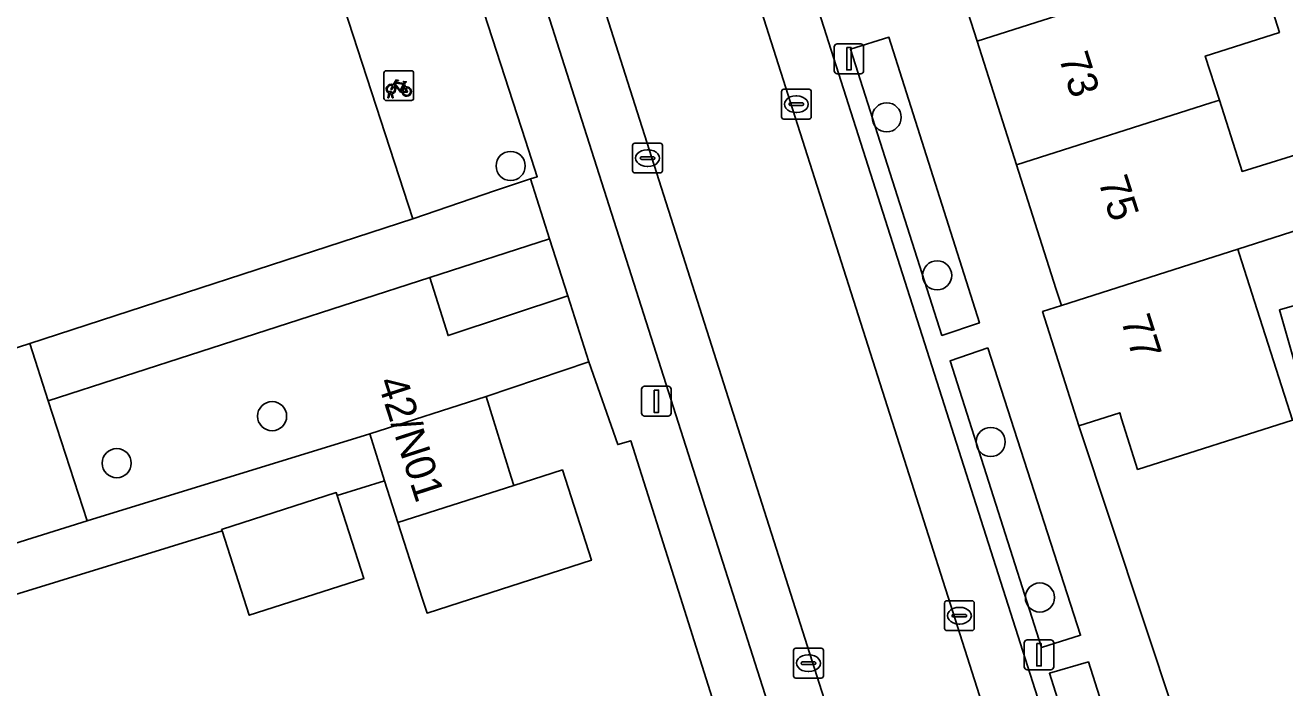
# Model space of a CAD drawing. Extents: x 159716 to 160783, y 383290 to 384031.
# Drawn here: x 160164.47 to 160206.79, y 383496.97 to 383519.22 of the extents above; entities that cross this region are included whole.
import ezdxf

# ---------------------------------------------------------------- set-up
doc = ezdxf.new("R2010")
doc.units = 0
for name, color, linetype in [('IMGEO_Boom', 7, 'Continuous'), ('IMGEO_Erf', 7, 'Continuous'), ('IMGEO_Fietsenrek', 7, 'Continuous'), ('IMGEO_Grasland_overig', 7, 'Continuous'), ('IMGEO_Groenvoorziening', 7, 'Continuous'), ('IMGEO_Kolk', 7, 'Continuous'), ('IMGEO_Lichtmast', 7, 'Continuous'), ('IMGEO_Pand', 7, 'Continuous'), ('IMGEO_Pand_nummerreeks', 7, 'Continuous'), ('IMGEO_Parkeervlak_open', 7, 'Continuous'), ('IMGEO_Rijbaan_lokaal_open', 7, 'Continuous'), ('IMGEO_Voetpad_open', 7, 'Continuous')]:
    doc.layers.add(name, color=color, linetype=linetype)

msp = doc.modelspace()

# ---------------------------------------------------------------- linework, layer by layer
at = {"layer": 'IMGEO_Boom'}
for centre in [(160193.412, 383516.124), (160180.78, 383514.491), (160195.107, 383510.818), (160172.767, 383506.09), (160196.907, 383505.224), (160167.549, 383504.512), (160198.56, 383499.999)]:
    msp.add_circle(centre, 0.489, dxfattribs=at)
at = {"layer": 'IMGEO_Erf'}
for points in [[(160205.752, 383521.653), (160206.607, 383518.975), (160204.116, 383518.179), (160204.587, 383516.705), (160205.353, 383514.305), (160207.805, 383515.062)], [(160208.524, 383512.755), (160205.207, 383511.696), (160205.253, 383511.552), (160205.858, 383509.657), (160207.04, 383505.953), (160201.843, 383504.304), (160201.304, 383506.003), (160201.241, 383506.203), (160199.868, 383505.763), (160203.111, 383495.995), (160207.309, 383482.802)], [(160207.828, 383505.379), (160206.604, 383509.664), (160210.537, 383510.788)], [(160150.634, 383478.026), (160168.912, 383473.579), (160192.457, 383481.099), (160186.486, 383500), (160184.817, 383505.264), (160184.377, 383505.133), (160183.402, 383507.916), (160179.961, 383506.748), (160180.803, 383504.044), (160180.889, 383503.767), (160182.522, 383504.282), (160183.493, 383501.254), (160179.435, 383499.947), (160177.973, 383499.476), (160177.821, 383499.947), (160176.993, 383502.519), (160176.547, 383503.922), (160174.954, 383503.431), (160175.851, 383500.643), (160171.999, 383499.403), (160171.086, 383502.238), (160163.828, 383500)]]:
    msp.add_lwpolyline(points, dxfattribs=at)
at = {"layer": 'IMGEO_Fietsenrek'}
for p, q in [((160176.598, 383517.689), (160177.439, 383517.689)), ((160177.439, 383517.689), (160176.598, 383517.689)), ((160176.523, 383516.764), (160176.523, 383517.605)), ((160176.523, 383517.605), (160176.523, 383516.764)), ((160177.21, 383517.238), (160177.246, 383517.143)), ((160177.523, 383517.614), (160177.523, 383516.773)), ((160177.523, 383516.773), (160177.523, 383517.614)), ((160176.65, 383516.773), (160176.689, 383516.933)), ((160176.719, 383516.921), (160176.684, 383516.773)), ((160176.761, 383516.945), (160176.76, 383516.949)), ((160176.802, 383516.773), (160176.768, 383516.915)), ((160176.792, 383516.956), (160176.793, 383516.949)), ((160176.8, 383516.919), (160176.835, 383516.773)), ((160177.448, 383516.689), (160176.607, 383516.689)), ((160176.607, 383516.689), (160177.448, 383516.689)), ((160176.684, 383516.773), (160176.65, 383516.773)), ((160176.835, 383516.773), (160176.802, 383516.773))]:
    msp.add_line(p, q, dxfattribs=at)
for points in [[(160176.836, 383517.215), (160176.931, 383517.379), (160177.017, 383517.365), (160177.019, 383517.356), (160176.963, 383517.345), (160176.936, 383517.3), (160177.192, 383517.259)], [(160177.179, 383517.234), (160176.922, 383517.275), (160176.905, 383517.246), (160177.072, 383517.026), (160177.179, 383517.234)], [(160177.192, 383517.259), (160177.217, 383517.308), (160177.211, 383517.312), (160177.188, 383517.316), (160177.176, 383517.323), (160177.175, 383517.326), (160177.177, 383517.331), (160177.272, 383517.316), (160177.274, 383517.306), (160177.264, 383517.293), (160177.252, 383517.287), (160177.238, 383517.293), (160177.21, 383517.238)], [(160176.857, 383517.163), (160176.805, 383517.073), (160176.765, 383517.048), (160176.766, 383517.095), (160176.821, 383517.189)], [(160177.132, 383516.971), (160177.082, 383516.971), (160176.891, 383517.222), (160176.872, 383517.19)], [(160177.227, 383517.136), (160177.197, 383517.213), (160177.088, 383516.995), (160177.131, 383516.995)], [(160177.161, 383516.995), (160177.281, 383516.994), (160177.237, 383517.108)], [(160177.257, 383517.115), (160177.312, 383516.97), (160177.162, 383516.97)]]:
    msp.add_lwpolyline(points, dxfattribs=at)
for centre, radius, start, end in [((160176.601, 383517.611), 0.0779, 92.4484, 184.2845), ((160176.601, 383517.611), 0.0779, 92.4484, 184.2845), ((160177.445, 383517.611), 0.0779, 2.4484, 94.2845), ((160177.445, 383517.611), 0.0779, 2.4484, 94.2845), ((160176.763, 383517.074), 0.159, 62.6766, 242.1369), ((160176.763, 383517.074), 0.129, 63.3192, 238.903), ((160176.743, 383516.945), 0.0499, 12.8025, 158.6934), ((160176.763, 383517.074), 0.159, 253.9967, 271.7867), ((160176.743, 383516.945), 0.0174, 12.8025, 163.4502), ((160176.763, 383517.074), 0.129, 253.415, 269.0204), ((160176.763, 383517.074), 0.129, 283.6043, 43.4302), ((160176.763, 383517.074), 0.159, 283.5766, 46.6042), ((160177.29, 383516.99), 0.159, 113.3408, 178.3217), ((160177.29, 383516.99), 0.159, 187.0065, 105.7708), ((160177.29, 383516.99), 0.129, 113.923, 177.9556), ((160177.29, 383516.99), 0.129, 188.6715, 104.5883), ((160176.601, 383516.767), 0.0779, 182.4484, 274.2845), ((160176.601, 383516.767), 0.0779, 182.4484, 274.2845), ((160177.445, 383516.767), 0.0779, 272.4484, 4.2845), ((160177.445, 383516.767), 0.0779, 272.4484, 4.2845)]:
    msp.add_arc(centre, radius, start, end, dxfattribs=at)
at = {"layer": 'IMGEO_Grasland_overig'}
for points in [[(160183.402, 383507.916), (160182.699, 383510.125), (160178.681, 383508.793), (160178.065, 383510.742), (160165.248, 383506.607), (160166.551, 383502.574), (160176.046, 383505.497), (160179.961, 383506.748)], [(160171.086, 383502.238), (160171.073, 383502.28), (160174.925, 383503.521), (160174.954, 383503.431), (160176.547, 383503.922), (160176.046, 383505.497), (160166.551, 383502.574), (160158.329, 383500), (160156.175, 383499.326), (160156.763, 383497.927), (160160.54, 383499.088), (160163.828, 383500)]]:
    msp.add_lwpolyline(points, close=True, dxfattribs=at)
at = {"layer": 'IMGEO_Groenvoorziening'}
for points in [[(160193.49, 383518.81), (160192.195, 383518.411), (160195.266, 383508.801), (160196.525, 383509.221)], [(160196.807, 383508.387), (160195.545, 383507.953), (160198.611, 383498.318), (160199.924, 383498.734)], [(160201.966, 383487.837), (160203.237, 383488.254), (160200.188, 383497.835), (160198.879, 383497.455), (160201.793, 383488.238)]]:
    msp.add_lwpolyline(points, close=True, dxfattribs=at)
at = {"layer": 'IMGEO_Kolk'}
for p, q in [((160189.878, 383516.138), (160189.878, 383516.99)), ((160189.953, 383517.064), (160190.805, 383517.064)), ((160190.366, 383516.844), (160190.391, 383516.844)), ((160190.879, 383516.99), (160190.879, 383516.138)), ((160190.137, 383516.558), (160190.137, 383516.57)), ((160190.575, 383516.521), (160190.177, 383516.521)), ((160190.18, 383516.607), (160190.578, 383516.607)), ((160190.621, 383516.57), (160190.621, 383516.558)), ((160190.805, 383516.064), (160189.953, 383516.064)), ((160190.389, 383516.284), (160190.364, 383516.284)), ((160184.878, 383514.329), (160184.878, 383515.181)), ((160184.953, 383515.255), (160185.805, 383515.255)), ((160185.879, 383515.181), (160185.879, 383514.329)), ((160185.137, 383514.749), (160185.137, 383514.761)), ((160185.575, 383514.712), (160185.177, 383514.712)), ((160185.18, 383514.798), (160185.578, 383514.798)), ((160185.366, 383515.035), (160185.391, 383515.035)), ((160185.621, 383514.761), (160185.621, 383514.749)), ((160185.389, 383514.475), (160185.364, 383514.475)), ((160185.805, 383514.255), (160184.953, 383514.255)), ((160195.43, 383499.89), (160196.282, 383499.89)), ((160195.355, 383498.964), (160195.355, 383499.816)), ((160195.843, 383499.67), (160195.868, 383499.67)), ((160196.356, 383499.816), (160196.356, 383498.964)), ((160195.614, 383499.384), (160195.614, 383499.396)), ((160196.052, 383499.347), (160195.654, 383499.347)), ((160195.657, 383499.433), (160196.055, 383499.433)), ((160195.866, 383499.11), (160195.841, 383499.11)), ((160196.098, 383499.396), (160196.098, 383499.384)), ((160196.282, 383498.89), (160195.43, 383498.89)), ((160190.285, 383497.37), (160190.285, 383498.222)), ((160190.36, 383498.296), (160191.212, 383498.296)), ((160191.286, 383498.222), (160191.286, 383497.37)), ((160190.544, 383497.79), (160190.544, 383497.802)), ((160190.587, 383497.839), (160190.985, 383497.839)), ((160190.773, 383498.076), (160190.798, 383498.076)), ((160191.028, 383497.802), (160191.028, 383497.79)), ((160190.982, 383497.753), (160190.584, 383497.753)), ((160190.796, 383497.516), (160190.771, 383497.516)), ((160191.212, 383497.296), (160190.36, 383497.296))]:
    msp.add_line(p, q, dxfattribs=at)
for points in [[(160189.878, 383516.138), (160189.878, 383516.99)], [(160189.953, 383517.064), (160190.805, 383517.064)], [(160190.879, 383516.99), (160190.879, 383516.138)], [(160190.805, 383516.064), (160189.953, 383516.064)], [(160184.878, 383514.329), (160184.878, 383515.181)], [(160184.953, 383515.255), (160185.805, 383515.255)], [(160185.879, 383515.181), (160185.879, 383514.329)], [(160185.805, 383514.255), (160184.953, 383514.255)], [(160195.43, 383499.89), (160196.282, 383499.89)], [(160195.355, 383498.964), (160195.355, 383499.816)], [(160196.356, 383499.816), (160196.356, 383498.964)], [(160196.282, 383498.89), (160195.43, 383498.89)], [(160190.285, 383497.37), (160190.285, 383498.222)], [(160190.36, 383498.296), (160191.212, 383498.296)], [(160191.286, 383498.222), (160191.286, 383497.37)], [(160191.212, 383497.296), (160190.36, 383497.296)]]:
    msp.add_lwpolyline(points, dxfattribs=at)
for centre, radius, start, end in [((160189.955, 383516.988), 0.0765, 91.552, 178.448), ((160189.955, 383516.988), 0.0765, 91.552, 178.448), ((160190.803, 383516.988), 0.0765, 1.552, 88.448), ((160190.803, 383516.988), 0.0765, 1.552, 88.448), ((160190.177, 383516.567), 0.0403, 85.8775, 175.7526), ((160190.174, 383516.557), 0.0366, 178.938, 274.7102), ((160190.578, 383516.564), 0.043, 264.8664, 352.4533), ((160190.582, 383516.569), 0.0386, 1.7309, 96.639), ((160189.955, 383516.14), 0.0765, 181.552, 268.448), ((160189.955, 383516.14), 0.0765, 181.552, 268.448), ((160190.803, 383516.14), 0.0765, 271.552, 358.448), ((160190.803, 383516.14), 0.0765, 271.552, 358.448), ((160184.955, 383515.179), 0.0765, 91.552, 178.448), ((160184.955, 383515.179), 0.0765, 91.552, 178.448), ((160185.803, 383515.179), 0.0765, 1.552, 88.448), ((160185.803, 383515.179), 0.0765, 1.552, 88.448), ((160185.177, 383514.758), 0.0403, 85.8775, 175.7526), ((160185.174, 383514.748), 0.0366, 178.938, 274.7102), ((160185.578, 383514.755), 0.043, 264.8664, 352.4533), ((160185.582, 383514.76), 0.0386, 1.7309, 96.639), ((160184.955, 383514.331), 0.0765, 181.552, 268.448), ((160184.955, 383514.331), 0.0765, 181.552, 268.448), ((160185.803, 383514.331), 0.0765, 271.552, 358.448), ((160185.803, 383514.331), 0.0765, 271.552, 358.448), ((160195.432, 383499.814), 0.0765, 91.552, 178.448), ((160195.432, 383499.814), 0.0765, 91.552, 178.448), ((160196.28, 383499.814), 0.0765, 1.552, 88.448), ((160196.28, 383499.814), 0.0765, 1.552, 88.448), ((160195.654, 383499.393), 0.0403, 85.8775, 175.7526), ((160195.651, 383499.383), 0.0366, 178.938, 274.7102), ((160196.055, 383499.39), 0.043, 264.8664, 352.4533), ((160196.059, 383499.395), 0.0386, 1.7309, 96.639), ((160195.432, 383498.966), 0.0765, 181.552, 268.448), ((160195.432, 383498.966), 0.0765, 181.552, 268.448), ((160196.28, 383498.966), 0.0765, 271.552, 358.448), ((160196.28, 383498.966), 0.0765, 271.552, 358.448), ((160190.362, 383498.22), 0.0765, 91.552, 178.448), ((160190.362, 383498.22), 0.0765, 91.552, 178.448), ((160191.21, 383498.22), 0.0765, 1.552, 88.448), ((160191.21, 383498.22), 0.0765, 1.552, 88.448), ((160190.584, 383497.799), 0.0403, 85.8775, 175.7526), ((160190.581, 383497.789), 0.0366, 178.938, 274.7102), ((160190.985, 383497.796), 0.043, 264.8664, 352.4533), ((160190.989, 383497.801), 0.0386, 1.7309, 96.639), ((160190.362, 383497.372), 0.0765, 181.552, 268.448), ((160190.362, 383497.372), 0.0765, 181.552, 268.448), ((160191.21, 383497.372), 0.0765, 271.552, 358.448), ((160191.21, 383497.372), 0.0765, 271.552, 358.448)]:
    msp.add_arc(centre, radius, start, end, dxfattribs=at)
for centre, major_axis, ratio, start_param, end_param in [((160190.365, 383516.564), (-0.387, 0.002), 0.722429, 4.712389, 7.853982), ((160190.39, 383516.564), (-0.39, 0.002), 0.717154, 1.570796, 4.712389), ((160185.365, 383514.755), (-0.387, 0.002), 0.722429, 4.712389, 7.853982), ((160185.39, 383514.755), (-0.39, 0.002), 0.717154, 1.570796, 4.712389), ((160195.842, 383499.39), (-0.387, 0.002), 0.722429, 4.712389, 7.853982), ((160195.867, 383499.39), (-0.39, 0.002), 0.717154, 1.570796, 4.712389), ((160190.772, 383497.796), (-0.387, 0.002), 0.722429, 4.712389, 7.853982), ((160190.797, 383497.796), (-0.39, 0.002), 0.717154, 1.570796, 4.712389)]:
    msp.add_ellipse(centre, major_axis=major_axis, ratio=ratio, start_param=start_param, end_param=end_param, dxfattribs=at)
at = {"layer": 'IMGEO_Lichtmast'}
for p, q in [((160191.749, 383518.589), (160192.539, 383518.589)), ((160192.539, 383518.589), (160191.749, 383518.589)), ((160191.649, 383517.689), (160191.649, 383518.489)), ((160191.649, 383518.489), (160191.649, 383517.689)), ((160192.639, 383518.489), (160192.639, 383517.689)), ((160192.639, 383517.689), (160192.639, 383518.489)), ((160192.539, 383517.589), (160191.749, 383517.589)), ((160191.749, 383517.589), (160192.539, 383517.589)), ((160185.281, 383507.093), (160186.071, 383507.093)), ((160186.071, 383507.093), (160185.281, 383507.093)), ((160185.181, 383506.193), (160185.181, 383506.993)), ((160185.181, 383506.993), (160185.181, 383506.193)), ((160186.171, 383506.993), (160186.171, 383506.193)), ((160186.171, 383506.193), (160186.171, 383506.993)), ((160186.071, 383506.093), (160185.281, 383506.093)), ((160185.281, 383506.093), (160186.071, 383506.093)), ((160198.033, 383497.677), (160198.033, 383498.477)), ((160198.033, 383498.477), (160198.033, 383497.677)), ((160198.133, 383498.577), (160198.923, 383498.577)), ((160198.923, 383498.577), (160198.133, 383498.577)), ((160199.023, 383498.477), (160199.023, 383497.677)), ((160199.023, 383497.677), (160199.023, 383498.477)), ((160198.923, 383497.577), (160198.133, 383497.577)), ((160198.133, 383497.577), (160198.923, 383497.577))]:
    msp.add_line(p, q, dxfattribs=at)
for points in [[(160192.069, 383518.464), (160192.219, 383518.464), (160192.219, 383517.714), (160192.069, 383517.714), (160192.069, 383518.464)], [(160185.601, 383506.968), (160185.751, 383506.968), (160185.751, 383506.218), (160185.601, 383506.218), (160185.601, 383506.968)], [(160198.453, 383498.452), (160198.603, 383498.452), (160198.603, 383497.702), (160198.453, 383497.702), (160198.453, 383498.452)]]:
    msp.add_lwpolyline(points, dxfattribs=at)
for centre, start, end in [((160191.749, 383518.489), 90, 180), ((160191.749, 383518.489), 90, 180), ((160192.539, 383518.489), 0, 90), ((160192.539, 383518.489), 360, 90), ((160191.749, 383517.689), 180, 270), ((160191.749, 383517.689), 180, 270), ((160192.539, 383517.689), 270, 0), ((160192.539, 383517.689), 270, 0), ((160185.281, 383506.993), 90, 180), ((160185.281, 383506.993), 90, 180), ((160186.071, 383506.993), 0, 90), ((160186.071, 383506.993), 360, 90), ((160185.281, 383506.193), 180, 270), ((160185.281, 383506.193), 180, 270), ((160186.071, 383506.193), 270, 0), ((160186.071, 383506.193), 270, 0), ((160198.133, 383498.477), 90, 180), ((160198.133, 383498.477), 90, 180), ((160198.923, 383498.477), 0, 90), ((160198.923, 383498.477), 360, 90), ((160198.133, 383497.677), 180, 270), ((160198.133, 383497.677), 180, 270), ((160198.923, 383497.677), 270, 0), ((160198.923, 383497.677), 270, 0)]:
    msp.add_arc(centre, 0.1, start, end, dxfattribs=at)
at = {"layer": 'IMGEO_Pand'}
for points in [[(160174.562, 383521.735), (160173.289, 383525.659), (160171.518, 383531.116), (160170.889, 383533.055), (160151.395, 383526.752), (160155.574, 383513.885), (160158.009, 383506.387), (160164.625, 383508.535), (160177.491, 383512.712)], [(160205.101, 383523.693), (160202.636, 383522.906), (160201.961, 383525.019), (160201.74, 383524.948), (160195.124, 383522.836), (160196.448, 383518.683), (160205.503, 383521.573), (160205.752, 383521.653)], [(160204.116, 383518.179), (160206.607, 383518.975), (160205.752, 383521.653), (160205.503, 383521.573), (160196.448, 383518.683), (160197.773, 383514.529), (160204.297, 383516.612), (160204.587, 383516.705)], [(160204.587, 383516.705), (160204.297, 383516.612), (160197.773, 383514.529), (160199.098, 383510.376), (160199.281, 383509.803), (160205.207, 383511.696), (160208.524, 383512.755), (160208.345, 383513.328), (160207.805, 383515.062), (160205.353, 383514.305)], [(160205.207, 383511.696), (160199.281, 383509.803), (160198.652, 383509.603), (160199.868, 383505.763), (160201.241, 383506.203), (160201.304, 383506.003), (160201.843, 383504.304), (160207.04, 383505.953), (160205.858, 383509.657), (160205.253, 383511.552)], [(160213.102, 383511.521), (160210.537, 383510.788), (160206.604, 383509.664), (160207.828, 383505.379), (160211.76, 383506.503), (160212.184, 383505.019), (160214.818, 383505.771)], [(160179.961, 383506.748), (160176.046, 383505.497), (160176.547, 383503.922), (160176.993, 383502.519), (160180.889, 383503.767), (160180.803, 383504.044)], [(160180.889, 383503.767), (160176.993, 383502.519), (160177.821, 383499.947), (160177.973, 383499.476), (160179.435, 383499.947), (160183.493, 383501.254), (160182.522, 383504.282)], [(160174.954, 383503.431), (160174.925, 383503.521), (160171.073, 383502.28), (160171.086, 383502.238), (160171.999, 383499.403), (160175.851, 383500.643)]]:
    msp.add_lwpolyline(points, close=True, dxfattribs=at)
at = {"layer": 'IMGEO_Parkeervlak_open'}
for points in [[(160171.032, 383554.077), (160194.15, 383481.64), (160194.475, 383480.623)], [(160179.499, 383550.191), (160183.339, 383538.075), (160184.32, 383535.005), (160201.568, 383480.906)], [(160203.107, 383482.164), (160181.483, 383549.94)], [(160196.465, 383480.441), (160179.566, 383533.468)]]:
    msp.add_lwpolyline(points, dxfattribs=at)
at = {"layer": 'IMGEO_Rijbaan_lokaal_open'}
msp.add_lwpolyline([(160184.32, 383535.005), (160179.566, 383533.468), (160196.465, 383480.441), (160201.568, 383480.906)], close=True, dxfattribs=at)
at = {"layer": 'IMGEO_Voetpad_open'}
for points in [[(160178.776, 383523.078), (160181.283, 383515.345), (160181.677, 383514.129), (160181.448, 383514.056), (160182.09, 383512.041), (160182.699, 383510.125), (160183.402, 383507.916), (160184.377, 383505.133), (160184.817, 383505.264), (160186.486, 383500), (160192.457, 383481.099), (160194.15, 383481.64), (160171.032, 383554.077)], [(160181.483, 383549.94), (160203.107, 383482.164)], [(160202.829, 383481.608), (160203.836, 383481.795), (160202.206, 383486.951), (160203.528, 383487.348), (160205.175, 383482.215), (160207.197, 383482.766), (160207.309, 383482.802), (160203.111, 383495.995), (160199.868, 383505.763), (160198.652, 383509.603), (160199.281, 383509.803), (160199.098, 383510.376), (160197.773, 383514.529), (160196.448, 383518.683), (160195.124, 383522.836), (160193.799, 383526.989)]]:
    msp.add_lwpolyline(points, dxfattribs=at)
for points in [[(160178.776, 383523.078), (160174.562, 383521.735), (160177.491, 383512.712), (160180.277, 383513.666), (160181.448, 383514.056), (160181.677, 383514.129), (160181.283, 383515.345)], [(160196.525, 383509.221), (160195.266, 383508.801), (160192.195, 383518.411), (160193.49, 383518.81)], [(160165.248, 383506.607), (160164.625, 383508.535), (160158.009, 383506.387), (160155.574, 383513.885), (160154.18, 383513.433), (160154.554, 383512.279), (160152.227, 383511.524), (160155.957, 383500), (160156.175, 383499.326), (160158.329, 383500), (160166.551, 383502.574)], [(160178.065, 383510.742), (160182.09, 383512.041), (160181.448, 383514.056), (160180.277, 383513.666), (160177.491, 383512.712), (160164.625, 383508.535), (160165.248, 383506.607)], [(160178.065, 383510.742), (160178.681, 383508.793), (160182.699, 383510.125), (160182.09, 383512.041)], [(160196.807, 383508.387), (160199.924, 383498.734), (160198.611, 383498.318), (160195.545, 383507.953)], [(160200.188, 383497.835), (160203.237, 383488.254), (160201.966, 383487.837), (160201.793, 383488.238), (160198.879, 383497.455)]]:
    msp.add_lwpolyline(points, close=True, dxfattribs=at)

# ---------------------------------------------------------------- texts
at = {"layer": 'IMGEO_Pand_nummerreeks'}
for s, rotation, p in [('73', 287.7099, (160199.184, 383518.135)), ('75', 287.7099, (160200.511, 383513.983)), ('77', 287.6985, (160201.269, 383509.319)), ('42/N01', 287.9105, (160176.296, 383507.25))]:
    msp.add_text(s, height=1, rotation=rotation, dxfattribs=at).set_placement(p)

doc.saveas('drawing.dxf')
